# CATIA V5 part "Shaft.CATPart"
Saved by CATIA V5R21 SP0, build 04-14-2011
Part number: Shaft
Bounding box of the stored display mesh (mm): x -10.997 to 10.997, y 0 to 134, z -10.875 to 10.875
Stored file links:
  D:\CATIA V5R21 E-RESOURCES\CATIA-V5R21\catia-v5r21-Prts\c12_catia_v5r21_prt\c12_catia_v5r21figr_12-54 to 56\Shaft.CATPart
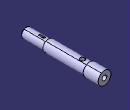
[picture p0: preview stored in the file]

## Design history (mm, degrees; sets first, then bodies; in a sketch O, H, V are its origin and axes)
Body1 (main body)
  Sketch1 on yz-plane, origin (0, 0, 0), H (0, 1, 0), V (0, 0, 1)
    line L1 (0, 0) -> (0, 8)
    line L2 (0, 8) -> (39, 8)
    line L3 (39, 8) -> (39, 9.5)
    line L4 (39, 9.5) -> (109, 9.5)
    line L5 (109, 9.5) -> (109, 11)
    line L6 (109, 11) -> (134, 11)
    line L7 (134, 11) -> (134, 0)
    point P7 (134, 0)
    line L8 (134, 0) -> (0, 0)
    length L1 = 8
    length L8 = 134
    length L7 = 11
    distance L4 L8 = 9.5
    length L6 = 25
    length L4 = 70
    vertical: L1 V, L3 V, L5 V, L7 V
    horizontal: L2 H, L4 H, L6 H, L8 H
    coincidence: P7 H
  Shaft1: profile Sketch1, axis edge of Sketch1, angle 360
  Chamfer1: length 1.5, angle 45, on 1 edge
  Sketch2 on xy-plane, origin (0, 0, 0), H (1, 0, 0), V (0, 1, 0)
    circle A1 centre (0, 97) radius 4.15
    point P1 (0, 97)
    reference projected line E1 (-11, 109) -> (11, 109) from edge of Shaft1
    radius A1 = 4.15
    distance E1 P1 = 12
    coincidence: P1 V
  Pocket1: profile Sketch2, direction (0, 0, -1), length 20, mirrored extent
  Sketch3 on face of Shaft1, origin (0, 134, 0), H (-1, 0, 0), V (0, 0, 1)
    circle A1 centre (0, 0) radius 4.15
    radius A1 = 4.15
  Pocket2: profile Sketch3, direction (0, -1, 0), length 44
  Sketch4 on yz-plane, origin (0, 0, 0), H (0, 1, 0), V (0, 0, 1)
    point P1 (23, 8)
    line L1 (23, 8) -> (33, 8)
    arc A1 centre (28, 12.899) radius 7 from (23, 8) to (33, 8) ccw
    reference projected line E1 (39, -9.5) -> (39, 9.5) from edge of Shaft1
    length L1 = 10
    distance L1 H = 8
    distance P1 E1 = 16
    radius A1 = 7
    horizontal: L1 H
  Pocket3: profile Sketch4, direction (-1, 0, 0), length 1.6, mirrored extent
